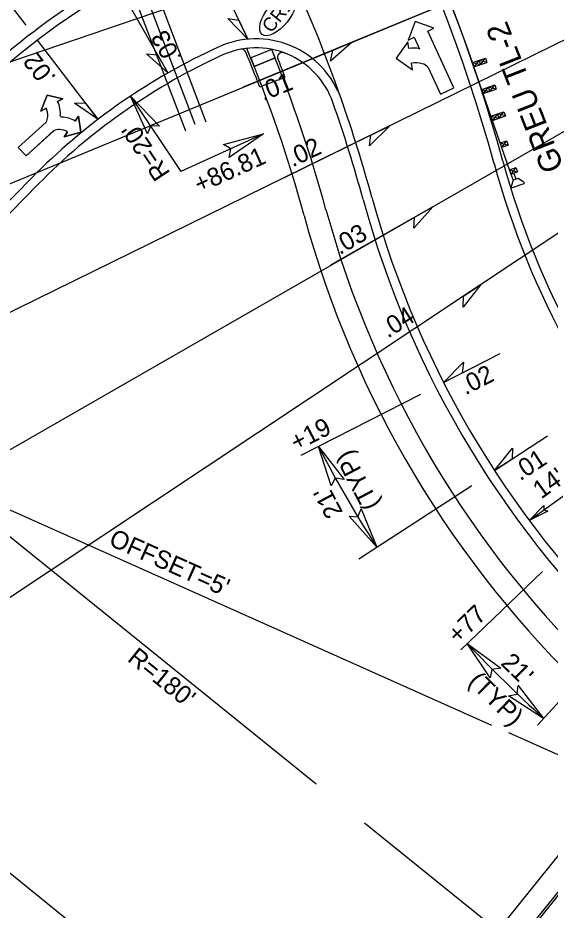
# Model space of a CAD drawing. Extents: x 1486489 to 1490134, y 497089 to 500876.
# Drawn here: x 1488524.4 to 1488642, y 499048.4 to 499245.3 of the extents above; entities that cross this region are included whole.
import ezdxf

# ---------------------------------------------------------------- set-up
doc = ezdxf.new("R2010")
doc.units = 0
for name, color, linetype in [('DEV PRELIMINARY STAMP CELL', 7, 'Continuous'), ('Gray Area Fill Shapes', 7, 'Continuous'), ('Pattern 5', 7, 'Continuous'), ('Prop DSN Text', 7, 'Continuous'), ('Prop Guardrail', 7, 'Continuous'), ('Prop Guardrail Anchor Unit CELL', 7, 'Continuous'), ('Prop Horizontal Alignment Station Label', 7, 'Continuous'), ('Prop North Arrow NAD83 for Plan Sheets CELL', 7, 'Continuous'), ('Prop Text', 7, 'Continuous'), ('Prop WCC CELL', 7, 'Continuous'), ('Scratch_Level_0', 7, 'Continuous'), ('Scratch_Level_5', 7, 'Continuous'), ('Sheet Block Title CELL', 7, 'Continuous'), ('Sheet Cutting Line CELL', 7, 'Continuous'), ('Sheet Data Field CELL', 7, 'Continuous'), ('Sheet Plan CELL', 7, 'Continuous'), ('Sheet Plot Border Inside CELL', 7, 'Continuous'), ('Sheet Plot Border Outside CELL', 7, 'Continuous'), ('Sheet Sticker Exception Certification CELL', 7, 'Continuous')]:
    doc.layers.add(name, color=color, linetype=linetype)

msp = doc.modelspace()

# ---------------------------------------------------------------- linework, layer by layer
at = {"layer": 'DEV PRELIMINARY STAMP CELL'}
for p, q in [((1488526.22, 499243.66), (1488506.63, 499269.31)), ((1488575.18, 499240.55), (1488564.77, 499262.63)), ((1488546.63, 499252.2), (1488557.55, 499233.1)), ((1488542.12, 499222.86), (1488528.76, 499240.34)), ((1488618.43, 499164.79), (1488630.9, 499171.16)), ((1488586.98, 499148.73), (1488613.4, 499162.22)), ((1488629.68, 499145.35), (1488641.41, 499152.99)), ((1488599.75, 499125.87), (1488624.65, 499142.08))]:
    msp.add_line(p, q, dxfattribs=at)
for points in [[(1488575.18, 499240.55), (1488570.81, 499245.13), (1488573.2, 499244.74)], [(1488557.55, 499233.1), (1488552.84, 499237.32), (1488555.25, 499237.12)], [(1488542.12, 499222.86), (1488536.89, 499226.42), (1488539.31, 499226.54)], [(1488618.43, 499164.79), (1488622.86, 499169.3), (1488622.55, 499166.89)], [(1488593.63, 499142), (1488590.82, 499150.69), (1488596.44, 499143.42), (1488594.49, 499143.7)], [(1488629.68, 499145.35), (1488633.62, 499150.3), (1488633.56, 499147.88)], [(1488600.26, 499136.9), (1488603.7, 499128.44), (1488597.56, 499135.28), (1488599.53, 499135.14)]]:
    msp.add_lwpolyline(points, close=True, dxfattribs=at)
msp.add_arc((1488809.02, 499262.12), 245, 207.0514, 213.0675, dxfattribs=at)
at = {"layer": 'Pattern 5'}
for p, q in [((1488580.47, 499238.3), (1488575.84, 499236.41)), ((1488581.22, 499236.45), (1488580.47, 499238.3)), ((1488575.84, 499236.41), (1488576.59, 499234.56)), ((1488576.59, 499234.56), (1488581.22, 499236.45))]:
    msp.add_line(p, q, dxfattribs=at)
msp.add_lwpolyline([(1488581.22, 499236.45), (1488581.22, 499236.45)], dxfattribs=at)
at = {"layer": 'Prop DSN Text'}
for p, q in [((1488402.29, 499158.9), (1488771.96, 499311.68)), ((1488775.29, 499304.32), (1488416.25, 499127.99)), ((1488432.18, 499098.05), (1488779.08, 499297.19)), ((1488783.32, 499290.32), (1488450, 499069.19)), ((1488591.1, 499258.8), (1488390.36, 499190.64))]:
    msp.add_line(p, q, dxfattribs=at)
at = {"layer": 'Prop Guardrail'}
msp.add_arc((1488292.94, 499121.08), 351, 19.0041, 40.0716, dxfattribs=at)
at = {"layer": 'Prop Guardrail Anchor Unit CELL'}
for p, q in [((1488624.81, 499235.38), (1488627.68, 499236.37)), ((1488626.25, 499235.88), (1488625.14, 499234.44)), ((1488626.25, 499235.88), (1488626.57, 499234.93)), ((1488628.01, 499235.42), (1488626.25, 499235.88)), ((1488626.57, 499234.93), (1488627.68, 499236.37)), ((1488627.68, 499236.37), (1488628.01, 499235.42)), ((1488624.81, 499235.38), (1488625.14, 499234.44)), ((1488624.81, 499235.38), (1488626.57, 499234.93)), ((1488633.12, 499211.27), (1488624.97, 499234.91)), ((1488625.14, 499234.44), (1488628.01, 499235.42)), ((1488626.85, 499229.47), (1488629.72, 499230.46)), ((1488628.28, 499229.97), (1488627.17, 499228.53)), ((1488628.28, 499229.97), (1488628.61, 499229.02)), ((1488630.04, 499229.52), (1488628.28, 499229.97)), ((1488628.61, 499229.02), (1488629.72, 499230.46)), ((1488629.72, 499230.46), (1488630.04, 499229.52)), ((1488626.85, 499229.47), (1488627.17, 499228.53)), ((1488626.85, 499229.47), (1488628.61, 499229.02)), ((1488627.17, 499228.53), (1488630.04, 499229.52)), ((1488628.88, 499223.56), (1488631.75, 499224.55)), ((1488630.32, 499224.06), (1488629.21, 499222.62)), ((1488630.32, 499224.06), (1488630.64, 499223.11)), ((1488632.08, 499223.61), (1488630.32, 499224.06)), ((1488630.64, 499223.11), (1488631.75, 499224.55)), ((1488631.75, 499224.55), (1488632.08, 499223.61)), ((1488628.88, 499223.56), (1488629.21, 499222.62)), ((1488628.88, 499223.56), (1488630.64, 499223.11)), ((1488629.21, 499222.62), (1488632.08, 499223.61)), ((1488630.92, 499217.65), (1488632.35, 499218.15)), ((1488632.35, 499218.15), (1488631.24, 499216.71)), ((1488632.35, 499218.15), (1488632.68, 499217.2)), ((1488630.92, 499217.65), (1488631.24, 499216.71)), ((1488630.92, 499217.65), (1488632.68, 499217.2)), ((1488631.24, 499216.71), (1488632.68, 499217.2)), ((1488632.96, 499211.74), (1488634.39, 499212.24)), ((1488634.39, 499212.24), (1488633.28, 499210.8)), ((1488634.39, 499212.24), (1488634.72, 499211.29)), ((1488632.96, 499211.74), (1488633.28, 499210.8)), ((1488632.96, 499211.74), (1488634.72, 499211.29)), ((1488633.28, 499210.8), (1488634.72, 499211.29)), ((1488633.29, 499210.8), (1488633.77, 499209.41)), ((1488634.45, 499209.65), (1488633.97, 499211.04)), ((1488633.77, 499209.41), (1488633.34, 499208.02)), ((1488633.44, 499207.73), (1488636.22, 499208.69)), ((1488634.93, 499209.81), (1488633.77, 499209.41)), ((1488636.12, 499208.98), (1488634.93, 499209.81)), ((1488636.12, 499208.98), (1488636.22, 499208.69)), ((1488633.34, 499208.02), (1488633.44, 499207.73))]:
    msp.add_line(p, q, dxfattribs=at)
at = {"layer": 'Prop Horizontal Alignment Station Label'}
for p, q in [((1488580.47, 499238.3), (1488575.84, 499236.41)), ((1488581.22, 499236.45), (1488576.59, 499234.56)), ((1488582.98, 499231.95), (1488578.3, 499230.17)), ((1488627.75, 499032.57), (1488666.32, 499080.39)), ((1488623.86, 499035.7), (1488655.57, 499075.03))]:
    msp.add_line(p, q, dxfattribs=at)
for centre, radius, start, end in [((1488292.94, 499121.08), 305.5, 15.2846, 22.6075), ((1488292.94, 499121.08), 310.5, 15.2846, 22.1798), ((1488809.02, 499262.12), 224.5, 195.2846, 226.3706), ((1488809.02, 499262.12), 229.5, 195.2846, 226.422)]:
    msp.add_arc(centre, radius, start, end, dxfattribs=at)
at = {"layer": 'Prop North Arrow NAD83 for Plan Sheets CELL'}
for p, q in [((1488582.98, 499231.95), (1488583.44, 499232.12)), ((1488578.3, 499230.17), (1488577.84, 499229.99)), ((1488628.14, 499032.25), (1488666.71, 499080.08))]:
    msp.add_line(p, q, dxfattribs=at)
for centre, radius, start, end in [((1488573.83, 499237.34), 1, 22.4839, 100.7387), ((1488292.94, 499121.08), 305, 20.92, 22.4839), ((1488582.76, 499236.63), 1, 70.2165, 201.7376), ((1488292.94, 499121.08), 311, 20.9189, 21.7376)]:
    msp.add_arc(centre, radius, start, end, dxfattribs=at)
at = {"layer": 'Prop Text'}
for p, q in [((1488566.03, 499222.24), (1488549.2, 499266.45)), ((1488544.56, 499264.58), (1488561.41, 499220.33))]:
    msp.add_line(p, q, dxfattribs=at)
at = {"layer": 'Prop WCC CELL'}
msp.add_ellipse((1488581.86, 499245.95), major_axis=(3.52, 4.36), ratio=0.462467, dxfattribs=at)
at = {"layer": 'Scratch_Level_0'}
for p, q in [((1488563.56, 499221.7), (1488547.08, 499265)), ((1488549.32, 499228.01), (1488560.43, 499211.38)), ((1488578.65, 499219.63), (1488560.43, 499211.38)), ((1488590.28, 499076.19), (1488506.26, 499143.96)), ((1488629.09, 499089.14), (1488506.26, 499143.96)), ((1488670.63, 499070.6), (1488632.82, 499087.48)), ((1488646.37, 499030.96), (1488600.96, 499067.58))]:
    msp.add_line(p, q, dxfattribs=at)
for points in [[(1488553.03, 499219.67), (1488549.32, 499228.01), (1488555.68, 499221.38), (1488553.71, 499221.45)], [(1488569.81, 499217.33), (1488578.65, 499219.63), (1488571.07, 499214.44), (1488571.45, 499216.37)]]:
    msp.add_lwpolyline(points, close=True, dxfattribs=at)
at = {"layer": 'Scratch_Level_5'}
for p, q in [((1488569.33, 499236.92), (1488568.13, 499236.36)), ((1488484.3, 499163.25), (1488528.89, 499208.54))]:
    msp.add_line(p, q, dxfattribs=at)
for centre, radius, start, end in [((1488292.94, 499121.08), 351, 15.2846, 40.0716), ((1488626.52, 499112.42), 163, 115.2255, 135.4445), ((1488577, 499220.64), 18, 19.3141, 115.2255), ((1488626.52, 499112.42), 137, 115.2255, 135.4445), ((1488292.94, 499121.08), 319, 15.2846, 19.3141), ((1488809.02, 499262.12), 184, 195.2846, 222.6475), ((1488809.02, 499262.12), 216, 195.2846, 227.2261)]:
    msp.add_arc(centre, radius, start, end, dxfattribs=at)
at = {"layer": 'Sheet Block Title CELL'}
msp.add_arc((1488292.94, 499121.08), 321, 19.3141, 31.1366, dxfattribs=at)
at = {"layer": 'Sheet Cutting Line CELL'}
msp.add_line((1488637.34, 499134.36), (1488648.69, 499142.55), dxfattribs=at)
at = {"layer": 'Sheet Data Field CELL'}
for p, q in [((1488625.94, 499251.33), (1488598.22, 499239.87)), ((1488598.22, 499239.87), (1488574.19, 499229.94)), ((1488606.54, 499221.44), (1488583.2, 499209.98)), ((1488616.03, 499203.59), (1488593.49, 499190.65)), ((1488626.66, 499186.39), (1488605, 499172.01)), ((1488640.28, 499123.09), (1488622.21, 499105.81)), ((1488639.14, 499089.21), (1488656.06, 499107.62))]:
    msp.add_line(p, q, dxfattribs=at)
for points in [[(1488598.22, 499239.87), (1488593.44, 499235.73), (1488593.94, 499238.11)], [(1488606.54, 499221.44), (1488602.04, 499217), (1488602.39, 499219.4)], [(1488616.03, 499203.59), (1488611.83, 499198.87), (1488612.02, 499201.29)], [(1488626.66, 499186.39), (1488622.77, 499181.4), (1488622.81, 499183.83)], [(1488628.75, 499099.62), (1488623.65, 499107.19), (1488631.06, 499101.76), (1488629.11, 499101.48)], [(1488634.91, 499097.92), (1488640.49, 499090.68), (1488632.75, 499095.63), (1488634.67, 499096.03)]]:
    msp.add_lwpolyline(points, close=True, dxfattribs=at)
msp.add_arc((1488887.49, 499359.42), 365, 223.7113, 227.4135, dxfattribs=at)
at = {"layer": 'Sheet Plan CELL'}
msp.add_line((1488778.61, 498850.05), (1488467.24, 499101.15), dxfattribs=at)
at = {"layer": 'Sheet Plot Border Inside CELL'}
for p, q in [((1488612.14, 499244.47), (1488610.59, 499240.34)), ((1488616.3, 499242.98), (1488612.14, 499244.47)), ((1488614.94, 499242.35), (1488616.3, 499242.98)), ((1488620.73, 499229.83), (1488614.94, 499242.35)), ((1488610.53, 499239.98), (1488607.96, 499236.37)), ((1488610.77, 499238.5), (1488610.53, 499239.98)), ((1488610.59, 499240.34), (1488611.95, 499240.97)), ((1488611.95, 499240.97), (1488613.14, 499238.38)), ((1488607.96, 499236.37), (1488611.57, 499233.8)), ((1488611.57, 499233.8), (1488611.35, 499235.24)), ((1488615.03, 499234.3), (1488617.74, 499228.44)), ((1488617.74, 499228.44), (1488620.73, 499229.83)), ((1488529.48, 499224.68), (1488530.89, 499228.2)), ((1488530.89, 499228.2), (1488534.35, 499227.37)), ((1488534.35, 499227.37), (1488533.19, 499226.77)), ((1488530.64, 499225.29), (1488529.48, 499224.68)), ((1488524.5, 499216.68), (1488530.63, 499222.26)), ((1488534.05, 499223.34), (1488533.78, 499223.64)), ((1488537.09, 499222.47), (1488537.8, 499223.57)), ((1488537.8, 499223.57), (1488538.33, 499220.02)), ((1488532.32, 499220.32), (1488526.23, 499214.78)), ((1488534.66, 499218.98), (1488535.38, 499220.08)), ((1488538.33, 499220.02), (1488534.66, 499218.98)), ((1488526.23, 499214.78), (1488524.5, 499216.68))]:
    msp.add_line(p, q, dxfattribs=at)
for points in [[(1488533.19, 499226.77), (1488534.35, 499227.37), (1488530.89, 499228.2), (1488529.48, 499224.68), (1488530.63, 499225.3)], [(1488530.64, 499222.26), (1488524.5, 499216.68), (1488526.23, 499214.78), (1488532.31, 499220.31)], [(1488531.01, 499223.44), (1488531.01, 499223.44)], [(1488534.05, 499223.34), (1488533.78, 499223.64)], [(1488535.39, 499220.06), (1488534.66, 499218.98), (1488538.33, 499220.02), (1488537.8, 499223.57), (1488537.09, 499222.47)], [(1488533.58, 499220.6), (1488533.58, 499220.6)]]:
    msp.add_lwpolyline(points, dxfattribs=at)
for centre, radius, start, end in [((1488611.79, 499234.17), 4.43, 72.3371, 103.2157), ((1488612.35, 499230.92), 4.43, 72.2434, 103.0969), ((1488613.08, 499232.69), 2.52, 39.4214, 75.7334)]:
    msp.add_arc(centre, radius, start, end, dxfattribs=at)
for centre, major_axis, start_param, end_param in [((1488527.28, 499223.16), (5.16, 4.69), 5.540317, 6.061346), ((1488527.28, 499223.16), (5.16, 4.69), 5.540317, 6.061346), ((1488527.28, 499223.16), (2.96, 2.69), 5.540317, 6.085081), ((1488527.28, 499223.16), (2.96, 2.69), 5.540317, 6.085081), ((1488528.88, 499223.15), (1.68, 1.53), 5.025308, 5.60123), ((1488528.88, 499223.15), (1.68, 1.53), 5.025308, 5.60123), ((1488532.95, 499216.92), (5.16, 4.69), 0.224676, 0.742959), ((1488532.95, 499216.92), (5.16, 4.69), 0.224676, 0.742959), ((1488533.09, 499218.51), (1.68, 1.53), 0.681955, 1.288737), ((1488533.09, 499218.51), (1.68, 1.53), 0.681955, 1.288737), ((1488532.95, 499216.92), (2.96, 2.69), 0.203036, 0.742869), ((1488532.95, 499216.92), (2.96, 2.69), 0.203036, 0.742869)]:
    msp.add_ellipse(centre, major_axis=major_axis, ratio=0.85, start_param=start_param, end_param=end_param, dxfattribs=at)
at = {"layer": 'Sheet Plot Border Outside CELL'}
msp.add_lwpolyline([(1488641.44, 499136.37), (1488637.34, 499134.36), (1488640.54, 499137.66), (1488640.54, 499136.67)], close=True, dxfattribs=at)
at = {"layer": 'Sheet Sticker Exception Certification CELL'}
for p, q in [((1488568.48, 499238.73), (1488567.28, 499238.16)), ((1488482.88, 499164.65), (1488527.47, 499209.94))]:
    msp.add_line(p, q, dxfattribs=at)
for centre, radius, start, end in [((1488292.94, 499121.08), 349, 15.2846, 40.0716), ((1488626.52, 499112.42), 161, 115.2255, 135.4445), ((1488577, 499220.64), 20, 19.3141, 115.2255), ((1488626.52, 499112.42), 139, 115.2255, 135.4445), ((1488292.94, 499121.08), 321, 15.2846, 19.3141), ((1488809.02, 499262.12), 186, 195.2846, 222.6475), ((1488809.02, 499262.12), 214, 195.2846, 227.2261)]:
    msp.add_arc(centre, radius, start, end, dxfattribs=at)

# ---------------------------------------------------------------- texts
at = {"layer": 'DEV PRELIMINARY STAMP CELL'}
for s, rotation, p in [('.02', 27.0514, (1488623.29, 499161.94)), ('+19', 27.0514, (1488585.88, 499149.53)), ('(TYP)', 117.8649, (1488604.4, 499137.9)), ('.01', 33.0675, (1488635.34, 499142.96)), ("21'", 117.8649, (1488596.29, 499136.13))]:
    msp.add_text(s, height=4, rotation=rotation, dxfattribs=at).set_placement(p)
at = {"layer": 'Gray Area Fill Shapes'}
for s, rotation, p in [('.03', 119.7468, (1488560.75, 499236.49)), ('.02', 127.3862, (1488533, 499232.11))]:
    msp.add_text(s, height=4, rotation=rotation, dxfattribs=at).set_placement(p)
at = {"layer": 'Prop Guardrail Anchor Unit CELL'}
msp.add_text('GREU TL-2', height=5, rotation=111.3982, dxfattribs=at).set_placement((1488645.06, 499212.3))
at = {"layer": 'Prop WCC CELL'}
msp.add_text('CR15', height=3, rotation=51.1156, dxfattribs=at).set_placement((1488580.38, 499241.76))
at = {"layer": 'Scratch_Level_0'}
for s, rotation, p in [("R=20'", 123.7346, (1488558.17, 499210.99)), ('+86.81', 24.3529, (1488564.48, 499206.51)), ("OFFSET=5'", 335.9508, (1488544.25, 499128.99)), ("R=180'", 321.1156, (1488548.38, 499103.5))]:
    msp.add_text(s, height=4, rotation=rotation, dxfattribs=at).set_placement(p)
at = {"layer": 'Sheet Cutting Line CELL'}
msp.add_text("14'", height=4, rotation=35.8006, dxfattribs=at).set_placement((1488639.99, 499138.96))
at = {"layer": 'Sheet Data Field CELL'}
for s, rotation, p in [('.01', 21.6691, (1488578.6, 499226.86)), ('.02', 25.5737, (1488585.09, 499212.25)), ('.03', 30.4087, (1488595.52, 499192.86)), ('.04', 32.2317, (1488606.12, 499174.47)), ('+77', 43.7113, (1488621.63, 499106.93)), ("21'", 315.5624, (1488630.86, 499102.66)), ('(TYP)', 315.5624, (1488623.67, 499098.51))]:
    msp.add_text(s, height=4, rotation=rotation, dxfattribs=at).set_placement(p)

doc.saveas('drawing.dxf')
